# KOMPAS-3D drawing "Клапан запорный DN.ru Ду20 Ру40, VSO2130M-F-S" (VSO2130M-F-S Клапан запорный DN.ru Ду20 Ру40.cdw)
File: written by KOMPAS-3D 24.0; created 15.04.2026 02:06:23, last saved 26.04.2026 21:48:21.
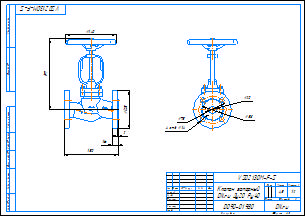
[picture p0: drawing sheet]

Document properties: Автор: DN.ru; Форматы листов документа: A3; Полное имя файла: VSO2130M-F-S Клапан запорный DN.ru Ду20 Ру40.m3d; Масса: 4.5; Наименование: Клапан запорный DN.ru Ду20 Ру40; Количество листов документа: 1; Примечание: D090-01980

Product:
- Part/product: Клапан запорный DN.ru Ду20 Ру40  | designation VSO2130M-F-S
    Масса: 4.5
    Раздел спецификации: Прочие изделия
    Примечание: D090-01980

Views: Вид 1, Вид:1, Проекционный вид 2
Referenced files in C:\Работа\VSO2130M-F-S Клапан запорный DN.ru\DN15\: VSO2130M-F-S DN15 PN40  Клапан запорный сильфонный DN.ru.m3d
Referenced files in C:\Работа\VSO2130M-F-S Клапан запорный DN.ru Ду-x Ру40\DN20\: VSO2130M-F-S Клапан запорный DN.ru Ду20 Ру40.m3d
Referenced files in C:\Program Files\ASCON\KOMPAS-3D v24\Templates\: Чертеж_DN.ru.cdt
Referenced files in C:\Работа\ГОТОВЫЕ ИСХОДНИКИ\VSO2130M-F-S Клапан запорный сальниковый DN.ru Ду15-100 Ру40\DN20\: VSO2130M-F-S Клапан запорный DN.ru Ду20 Ру40.m3d
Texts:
  VSO2130M-F-S
  Чертеж_DN.ru.cdt
  Клапан запорный
  DN.ru Ду20 Ру40
  Клапан запорный DN.ru Ду20 Ру40
  VSO2130M-F-S Клапан запорный DN.ru Ду20 Ру40
Dimensions and other numbers on the sheet: 0; 3; 2; 4; 105; 16; 197; 140; 150; 5; 20; 58; 75; 4 отв.; 14; 1:2; 1; 4,5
